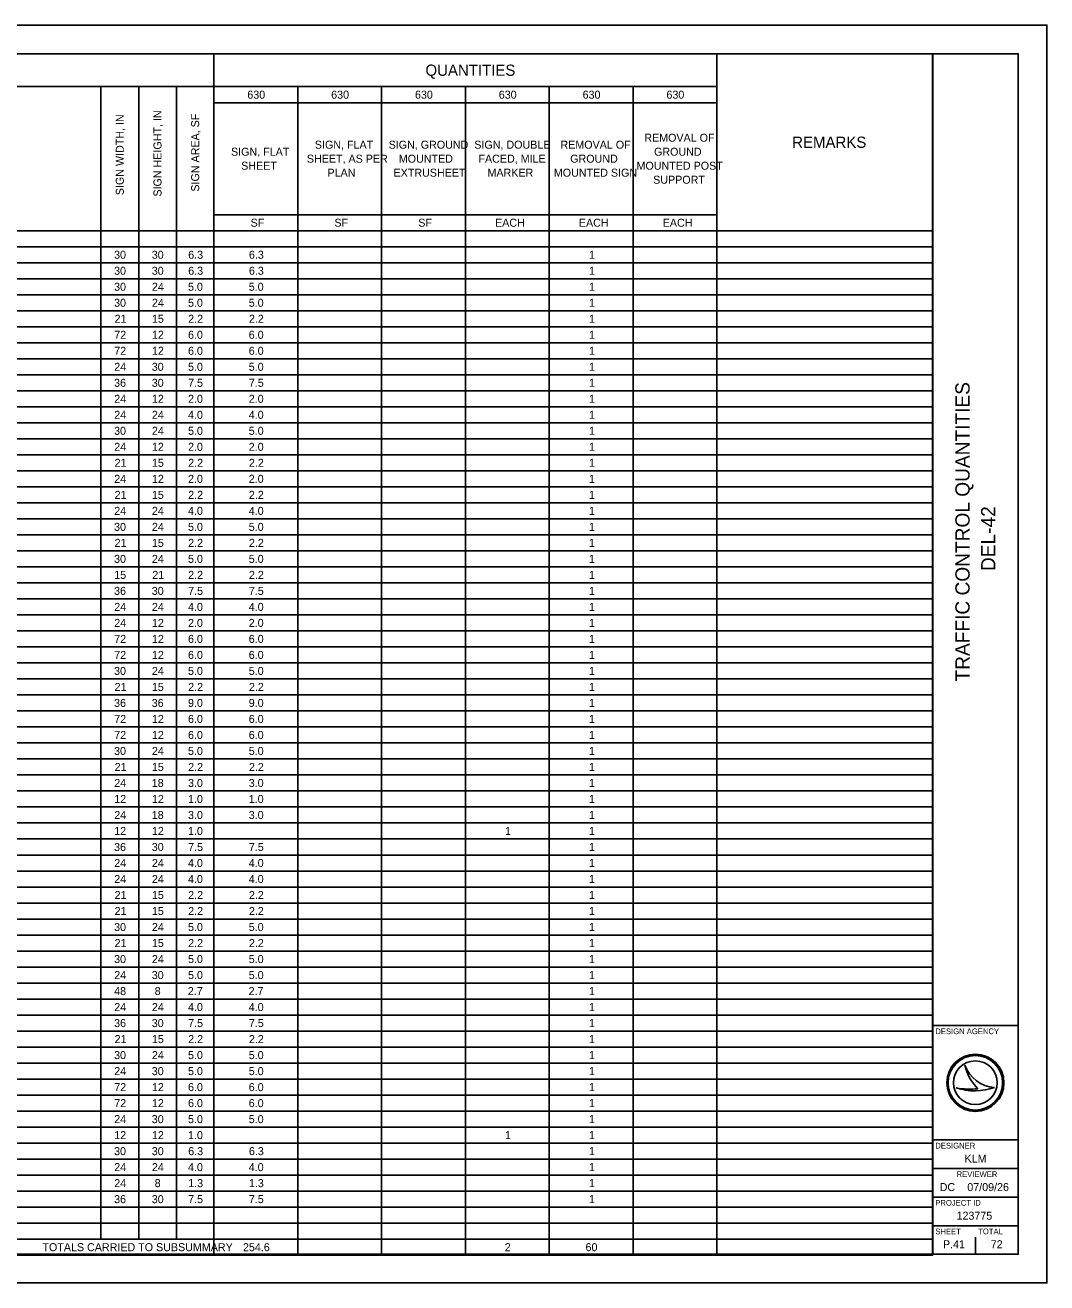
# Model space of a CAD drawing. Extents: x 0 to 34, y 0 to 22.
# Drawn here: x 16.13 to 34, y 0 to 22 of the extents above; entities that cross this region are included whole.
import ezdxf

# ---------------------------------------------------------------- set-up
doc = ezdxf.new("R2010")
doc.units = 0
for name, color, linetype in [('Default', 7, 'Continuous'), ('SH_Border', 7, 'Continuous'), ('SH_Cut_Line', 7, 'Continuous'), ('SH_Data', 7, 'Continuous')]:
    doc.layers.add(name, color=color, linetype=linetype)

msp = doc.modelspace()

# ---------------------------------------------------------------- linework, layer by layer
at = {"layer": 'SH_Border'}
for p, q in [((32, 0.5), (32, 21.5)), ((32, 4.5), (33.5, 4.5)), ((32, 2.5), (33.5, 2.5)), ((32, 2), (33.5, 2)), ((32, 1.5), (33.5, 1.5)), ((32, 1), (33.5, 1))]:
    msp.add_line(p, q, dxfattribs=at)
msp.add_lwpolyline([(1.5, 21.5), (33.5, 21.5), (33.5, 0.5), (1.5, 0.5)], close=True, dxfattribs=at)
at = {"layer": 'SH_Cut_Line'}
msp.add_lwpolyline([(0, 0), (34, 0), (34, 22), (0, 22)], close=True, dxfattribs=at)
at = {"layer": 'SH_Data'}
for p, q in [((1.5, 21.5), (32.004, 21.5)), ((19.436, 21.5), (19.436, 0.484)), ((28.232, 21.5), (28.232, 0.484)), ((32.004, 21.5), (32.004, 0.484)), ((1.5, 20.924), (28.232, 20.924)), ((17.46, 20.924), (17.46, 0.764)), ((18.119, 20.924), (18.119, 0.764)), ((18.778, 20.924), (18.778, 0.764)), ((20.902, 20.924), (20.902, 0.484)), ((22.368, 20.924), (22.368, 0.484)), ((23.834, 20.924), (23.834, 0.484)), ((25.3, 20.924), (25.3, 0.484)), ((26.766, 20.924), (26.766, 0.484)), ((19.436, 20.644), (28.232, 20.644)), ((19.436, 18.684), (28.232, 18.684)), ((1.5, 18.404), (32.004, 18.404)), ((1.5, 18.124), (32.004, 18.124)), ((1.5, 17.844), (32.004, 17.844)), ((1.5, 17.564), (32.004, 17.564)), ((1.5, 17.284), (32.004, 17.284)), ((1.5, 17.004), (32.004, 17.004)), ((1.5, 16.724), (32.004, 16.724)), ((1.5, 16.444), (32.004, 16.444)), ((1.5, 16.164), (32.004, 16.164)), ((1.5, 15.884), (32.004, 15.884)), ((1.5, 15.604), (32.004, 15.604)), ((1.5, 15.324), (32.004, 15.324)), ((1.5, 15.044), (32.004, 15.044)), ((1.5, 14.764), (32.004, 14.764)), ((1.5, 14.484), (32.004, 14.484)), ((1.5, 14.204), (32.004, 14.204)), ((1.5, 13.924), (32.004, 13.924)), ((1.5, 13.644), (32.004, 13.644)), ((1.5, 13.364), (32.004, 13.364)), ((1.5, 13.084), (32.004, 13.084)), ((1.5, 12.804), (32.004, 12.804)), ((1.5, 12.524), (32.004, 12.524)), ((1.5, 12.244), (32.004, 12.244)), ((1.5, 11.964), (32.004, 11.964)), ((1.5, 11.684), (32.004, 11.684)), ((1.5, 11.404), (32.004, 11.404)), ((1.5, 11.124), (32.004, 11.124)), ((1.5, 10.844), (32.004, 10.844)), ((1.5, 10.564), (32.004, 10.564)), ((1.5, 10.284), (32.004, 10.284)), ((1.5, 10.004), (32.004, 10.004)), ((1.5, 9.724), (32.004, 9.724)), ((1.5, 9.444), (32.004, 9.444)), ((1.5, 9.164), (32.004, 9.164)), ((1.5, 8.884), (32.004, 8.884)), ((1.5, 8.604), (32.004, 8.604)), ((1.5, 8.324), (32.004, 8.324)), ((1.5, 8.044), (32.004, 8.044)), ((1.5, 7.764), (32.004, 7.764)), ((1.5, 7.484), (32.004, 7.484)), ((1.5, 7.204), (32.004, 7.204)), ((1.5, 6.924), (32.004, 6.924)), ((1.5, 6.644), (32.004, 6.644)), ((1.5, 6.364), (32.004, 6.364)), ((1.5, 6.084), (32.004, 6.084)), ((1.5, 5.804), (32.004, 5.804)), ((1.5, 5.524), (32.004, 5.524)), ((1.5, 5.244), (32.004, 5.244)), ((1.5, 4.964), (32.004, 4.964)), ((1.5, 4.684), (32.004, 4.684)), ((1.5, 4.404), (32.004, 4.404)), ((1.5, 4.124), (32.004, 4.124)), ((1.5, 3.844), (32.004, 3.844)), ((32.567, 3.81), (32.567, 3.81)), ((1.5, 3.564), (32.004, 3.564)), ((32.417, 3.41), (32.417, 3.41)), ((32.75, 3.5), (32.75, 3.5)), ((33.087, 3.419), (33.087, 3.419)), ((1.5, 3.284), (32.004, 3.284)), ((1.5, 3.004), (32.004, 3.004)), ((1.5, 2.724), (32.004, 2.724)), ((1.5, 2.444), (32.004, 2.444)), ((1.5, 2.164), (32.004, 2.164)), ((1.5, 1.884), (32.004, 1.884)), ((1.5, 1.604), (32.004, 1.604)), ((1.5, 1.324), (32.004, 1.324)), ((1.5, 1.044), (32.004, 1.044)), ((1.5, 0.764), (32.004, 0.764)), ((32.375, 0.675), (32.375, 0.675)), ((32.75, 0.5), (32.75, 0.8)), ((1.5, 0.484), (32.004, 0.484))]:
    msp.add_line(p, q, dxfattribs=at)
for radius in [0.5, 0.477, 0.477, 0.382]:
    msp.add_circle((32.75, 3.5), radius, dxfattribs=at)
for centre, radius, start, end in [((33.116, 3.998), 0.58, 198.9257, 198.9319), ((33.347, 3.97), 0.796, 191.6379, 191.6421), ((33.116, 3.998), 0.58, 198.9319, 267.1657), ((33.347, 3.97), 0.796, 191.6421, 226.0947), ((32.739, 4.37), 1.013, 251.4576, 290.0832), ((32.648, 4.654), 1.266, 259.4964, 259.4995), ((32.739, 4.37), 1.013, 251.4527, 251.4576), ((32.648, 4.654), 1.266, 259.4995, 276.6672)]:
    msp.add_arc(centre, radius, start, end, dxfattribs=at)

# ---------------------------------------------------------------- texts
at = {"layer": 'Default'}
for s, height, p in [('QUANTITIES', 0.196, (23.134, 21.114)), ('630', 0.14, (20.019, 20.714)), ('630', 0.14, (21.485, 20.714)), ('630', 0.14, (22.951, 20.714)), ('630', 0.14, (24.416, 20.714)), ('630', 0.14, (25.882, 20.714)), ('630', 0.14, (27.348, 20.714)), ('REMOVAL OF ', 0.14, (26.961, 19.961)), ('REMARKS', 0.196, (29.547, 19.854)), ('SIGN, FLAT ', 0.14, (19.734, 19.716)), ('SIGN, FLAT ', 0.14, (21.2, 19.839)), ('SIGN, GROUND ', 0.14, (22.49, 19.839)), ('SIGN, DOUBLE ', 0.14, (23.988, 19.839)), ('REMOVAL OF ', 0.14, (25.495, 19.839)), ('GROUND ', 0.14, (27.131, 19.716)), ('SHEET', 0.14, (19.911, 19.471)), ('SHEET, AS PER ', 0.14, (21.06, 19.594)), ('MOUNTED ', 0.14, (22.668, 19.594)), ('FACED, MILE ', 0.14, (24.061, 19.594)), ('GROUND ', 0.14, (25.665, 19.594)), ('MOUNTED POST ', 0.14, (26.825, 19.471)), ('PLAN', 0.14, (21.421, 19.349)), ('EXTRUSHEET', 0.14, (22.576, 19.349)), ('MARKER', 0.14, (24.219, 19.349)), ('MOUNTED SIGN', 0.14, (25.379, 19.349)), ('SUPPORT', 0.14, (27.116, 19.226)), ('SF', 0.14, (20.076, 18.474)), ('SF', 0.14, (21.542, 18.474)), ('SF', 0.14, (23.008, 18.474)), ('EACH', 0.14, (24.351, 18.474)), ('EACH', 0.14, (25.817, 18.474)), ('EACH', 0.14, (27.283, 18.474)), ('30', 0.14, (17.689, 17.914)), ('30', 0.14, (18.348, 17.914)), ('6.3', 0.14, (18.985, 17.914)), ('6.3', 0.14, (20.047, 17.914)), ('1', 0.14, (25.992, 17.914)), ('30', 0.14, (17.689, 17.634)), ('30', 0.14, (18.348, 17.634)), ('6.3', 0.14, (18.985, 17.634)), ('6.3', 0.14, (20.047, 17.634)), ('1', 0.14, (25.992, 17.634)), ('30', 0.14, (17.689, 17.354)), ('24', 0.14, (18.351, 17.354)), ('5.0', 0.14, (18.982, 17.354)), ('5.0', 0.14, (20.044, 17.354)), ('1', 0.14, (25.992, 17.354)), ('30', 0.14, (17.689, 17.074)), ('24', 0.14, (18.351, 17.074)), ('5.0', 0.14, (18.982, 17.074)), ('5.0', 0.14, (20.044, 17.074)), ('1', 0.14, (25.992, 17.074)), ('21', 0.14, (17.698, 16.794)), ('15', 0.14, (18.35, 16.794)), ('2.2', 0.14, (18.985, 16.794)), ('2.2', 0.14, (20.047, 16.794)), ('1', 0.14, (25.992, 16.794)), ('72', 0.14, (17.692, 16.514)), ('12', 0.14, (18.351, 16.514)), ('6.0', 0.14, (18.982, 16.514)), ('6.0', 0.14, (20.044, 16.514)), ('1', 0.14, (25.992, 16.514)), ('72', 0.14, (17.692, 16.234)), ('12', 0.14, (18.351, 16.234)), ('6.0', 0.14, (18.982, 16.234)), ('6.0', 0.14, (20.044, 16.234)), ('1', 0.14, (25.992, 16.234)), ('24', 0.14, (17.692, 15.954)), ('30', 0.14, (18.348, 15.954)), ('5.0', 0.14, (18.982, 15.954)), ('5.0', 0.14, (20.044, 15.954)), ('1', 0.14, (25.992, 15.954)), ('36', 0.14, (17.689, 15.674)), ('30', 0.14, (18.348, 15.674)), ('7.5', 0.14, (18.984, 15.674)), ('7.5', 0.14, (20.046, 15.674)), ('1', 0.14, (25.992, 15.674)), ('24', 0.14, (17.692, 15.394)), ('12', 0.14, (18.351, 15.394)), ('2.0', 0.14, (18.982, 15.394)), ('2.0', 0.14, (20.044, 15.394)), ('1', 0.14, (25.992, 15.394)), ('24', 0.14, (17.692, 15.114)), ('24', 0.14, (18.351, 15.114)), ('4.0', 0.14, (18.982, 15.114)), ('4.0', 0.14, (20.044, 15.114)), ('1', 0.14, (25.992, 15.114)), ('30', 0.14, (17.689, 14.834)), ('24', 0.14, (18.351, 14.834)), ('5.0', 0.14, (18.982, 14.834)), ('5.0', 0.14, (20.044, 14.834)), ('1', 0.14, (25.992, 14.834)), ('24', 0.14, (17.692, 14.554)), ('12', 0.14, (18.351, 14.554)), ('2.0', 0.14, (18.982, 14.554)), ('2.0', 0.14, (20.044, 14.554)), ('1', 0.14, (25.992, 14.554)), ('21', 0.14, (17.698, 14.274)), ('15', 0.14, (18.35, 14.274)), ('2.2', 0.14, (18.985, 14.274)), ('2.2', 0.14, (20.047, 14.274)), ('1', 0.14, (25.992, 14.274)), ('24', 0.14, (17.692, 13.994)), ('12', 0.14, (18.351, 13.994)), ('2.0', 0.14, (18.982, 13.994)), ('2.0', 0.14, (20.044, 13.994)), ('1', 0.14, (25.992, 13.994)), ('21', 0.14, (17.698, 13.714)), ('15', 0.14, (18.35, 13.714)), ('2.2', 0.14, (18.985, 13.714)), ('2.2', 0.14, (20.047, 13.714)), ('1', 0.14, (25.992, 13.714)), ('24', 0.14, (17.692, 13.434)), ('24', 0.14, (18.351, 13.434)), ('4.0', 0.14, (18.982, 13.434)), ('4.0', 0.14, (20.044, 13.434)), ('1', 0.14, (25.992, 13.434)), ('30', 0.14, (17.689, 13.154)), ('24', 0.14, (18.351, 13.154)), ('5.0', 0.14, (18.982, 13.154)), ('5.0', 0.14, (20.044, 13.154)), ('1', 0.14, (25.992, 13.154)), ('21', 0.14, (17.698, 12.874)), ('15', 0.14, (18.35, 12.874)), ('2.2', 0.14, (18.985, 12.874)), ('2.2', 0.14, (20.047, 12.874)), ('1', 0.14, (25.992, 12.874)), ('30', 0.14, (17.689, 12.594)), ('24', 0.14, (18.351, 12.594)), ('5.0', 0.14, (18.982, 12.594)), ('5.0', 0.14, (20.044, 12.594)), ('1', 0.14, (25.992, 12.594)), ('15', 0.14, (17.691, 12.314)), ('21', 0.14, (18.357, 12.314)), ('2.2', 0.14, (18.985, 12.314)), ('2.2', 0.14, (20.047, 12.314)), ('1', 0.14, (25.992, 12.314)), ('36', 0.14, (17.689, 12.034)), ('30', 0.14, (18.348, 12.034)), ('7.5', 0.14, (18.984, 12.034)), ('7.5', 0.14, (20.046, 12.034)), ('1', 0.14, (25.992, 12.034)), ('24', 0.14, (17.692, 11.754)), ('24', 0.14, (18.351, 11.754)), ('4.0', 0.14, (18.982, 11.754)), ('4.0', 0.14, (20.044, 11.754)), ('1', 0.14, (25.992, 11.754)), ('24', 0.14, (17.692, 11.474)), ('12', 0.14, (18.351, 11.474)), ('2.0', 0.14, (18.982, 11.474)), ('2.0', 0.14, (20.044, 11.474)), ('1', 0.14, (25.992, 11.474)), ('72', 0.14, (17.692, 11.194)), ('12', 0.14, (18.351, 11.194)), ('6.0', 0.14, (18.982, 11.194)), ('6.0', 0.14, (20.044, 11.194)), ('1', 0.14, (25.992, 11.194)), ('72', 0.14, (17.692, 10.914)), ('12', 0.14, (18.351, 10.914)), ('6.0', 0.14, (18.982, 10.914)), ('6.0', 0.14, (20.044, 10.914)), ('1', 0.14, (25.992, 10.914)), ('30', 0.14, (17.689, 10.634)), ('24', 0.14, (18.351, 10.634)), ('5.0', 0.14, (18.982, 10.634)), ('5.0', 0.14, (20.044, 10.634)), ('1', 0.14, (25.992, 10.634)), ('21', 0.14, (17.698, 10.354)), ('15', 0.14, (18.35, 10.354)), ('2.2', 0.14, (18.985, 10.354)), ('2.2', 0.14, (20.047, 10.354)), ('1', 0.14, (25.992, 10.354)), ('36', 0.14, (17.689, 10.074)), ('36', 0.14, (18.347, 10.074)), ('9.0', 0.14, (18.982, 10.074)), ('9.0', 0.14, (20.044, 10.074)), ('1', 0.14, (25.992, 10.074)), ('72', 0.14, (17.692, 9.794)), ('12', 0.14, (18.351, 9.794)), ('6.0', 0.14, (18.982, 9.794)), ('6.0', 0.14, (20.044, 9.794)), ('1', 0.14, (25.992, 9.794)), ('72', 0.14, (17.692, 9.514)), ('12', 0.14, (18.351, 9.514)), ('6.0', 0.14, (18.982, 9.514)), ('6.0', 0.14, (20.044, 9.514)), ('1', 0.14, (25.992, 9.514)), ('30', 0.14, (17.689, 9.234)), ('24', 0.14, (18.351, 9.234)), ('5.0', 0.14, (18.982, 9.234)), ('5.0', 0.14, (20.044, 9.234)), ('1', 0.14, (25.992, 9.234)), ('21', 0.14, (17.698, 8.954)), ('15', 0.14, (18.35, 8.954)), ('2.2', 0.14, (18.985, 8.954)), ('2.2', 0.14, (20.047, 8.954)), ('1', 0.14, (25.992, 8.954)), ('24', 0.14, (17.692, 8.674)), ('18', 0.14, (18.348, 8.674)), ('3.0', 0.14, (18.982, 8.674)), ('3.0', 0.14, (20.044, 8.674)), ('1', 0.14, (25.992, 8.674)), ('12', 0.14, (17.692, 8.394)), ('12', 0.14, (18.351, 8.394)), ('1.0', 0.14, (18.982, 8.394)), ('1.0', 0.14, (20.044, 8.394)), ('1', 0.14, (25.992, 8.394)), ('24', 0.14, (17.692, 8.114)), ('18', 0.14, (18.348, 8.114)), ('3.0', 0.14, (18.982, 8.114)), ('3.0', 0.14, (20.044, 8.114)), ('1', 0.14, (25.992, 8.114)), ('12', 0.14, (17.692, 7.834)), ('12', 0.14, (18.351, 7.834)), ('1.0', 0.14, (18.982, 7.834)), ('1', 0.14, (24.526, 7.834)), ('1', 0.14, (25.992, 7.834)), ('36', 0.14, (17.689, 7.554)), ('30', 0.14, (18.348, 7.554)), ('7.5', 0.14, (18.984, 7.554)), ('7.5', 0.14, (20.046, 7.554)), ('1', 0.14, (25.992, 7.554)), ('24', 0.14, (17.692, 7.274)), ('24', 0.14, (18.351, 7.274)), ('4.0', 0.14, (18.982, 7.274)), ('4.0', 0.14, (20.044, 7.274)), ('1', 0.14, (25.992, 7.274)), ('24', 0.14, (17.692, 6.994)), ('24', 0.14, (18.351, 6.994)), ('4.0', 0.14, (18.982, 6.994)), ('4.0', 0.14, (20.044, 6.994)), ('1', 0.14, (25.992, 6.994)), ('21', 0.14, (17.698, 6.714)), ('15', 0.14, (18.35, 6.714)), ('2.2', 0.14, (18.985, 6.714)), ('2.2', 0.14, (20.047, 6.714)), ('1', 0.14, (25.992, 6.714)), ('21', 0.14, (17.698, 6.434)), ('15', 0.14, (18.35, 6.434)), ('2.2', 0.14, (18.985, 6.434)), ('2.2', 0.14, (20.047, 6.434)), ('1', 0.14, (25.992, 6.434)), ('30', 0.14, (17.689, 6.154)), ('24', 0.14, (18.351, 6.154)), ('5.0', 0.14, (18.982, 6.154)), ('5.0', 0.14, (20.044, 6.154)), ('1', 0.14, (25.992, 6.154)), ('21', 0.14, (17.698, 5.874)), ('15', 0.14, (18.35, 5.874)), ('2.2', 0.14, (18.985, 5.874)), ('2.2', 0.14, (20.047, 5.874)), ('1', 0.14, (25.992, 5.874)), ('30', 0.14, (17.689, 5.594)), ('24', 0.14, (18.351, 5.594)), ('5.0', 0.14, (18.982, 5.594)), ('5.0', 0.14, (20.044, 5.594)), ('1', 0.14, (25.992, 5.594)), ('24', 0.14, (17.692, 5.314)), ('30', 0.14, (18.348, 5.314)), ('5.0', 0.14, (18.982, 5.314)), ('5.0', 0.14, (20.044, 5.314)), ('1', 0.14, (25.992, 5.314)), ('48', 0.14, (17.69, 5.034)), ('8', 0.14, (18.399, 5.034)), ('2.7', 0.14, (18.979, 5.034)), ('2.7', 0.14, (20.041, 5.034)), ('1', 0.14, (25.992, 5.034)), ('24', 0.14, (17.692, 4.754)), ('24', 0.14, (18.351, 4.754)), ('4.0', 0.14, (18.982, 4.754)), ('4.0', 0.14, (20.044, 4.754)), ('1', 0.14, (25.992, 4.754)), ('36', 0.14, (17.689, 4.474)), ('30', 0.14, (18.348, 4.474)), ('7.5', 0.14, (18.984, 4.474)), ('7.5', 0.14, (20.046, 4.474)), ('1', 0.14, (25.992, 4.474)), ('21', 0.14, (17.698, 4.194)), ('15', 0.14, (18.35, 4.194)), ('2.2', 0.14, (18.985, 4.194)), ('2.2', 0.14, (20.047, 4.194)), ('1', 0.14, (25.992, 4.194)), ('30', 0.14, (17.689, 3.914)), ('24', 0.14, (18.351, 3.914)), ('5.0', 0.14, (18.982, 3.914)), ('5.0', 0.14, (20.044, 3.914)), ('1', 0.14, (25.992, 3.914)), ('24', 0.14, (17.692, 3.634)), ('30', 0.14, (18.348, 3.634)), ('5.0', 0.14, (18.982, 3.634)), ('5.0', 0.14, (20.044, 3.634)), ('1', 0.14, (25.992, 3.634)), ('72', 0.14, (17.692, 3.354)), ('12', 0.14, (18.351, 3.354)), ('6.0', 0.14, (18.982, 3.354)), ('6.0', 0.14, (20.044, 3.354)), ('1', 0.14, (25.992, 3.354)), ('72', 0.14, (17.692, 3.074)), ('12', 0.14, (18.351, 3.074)), ('6.0', 0.14, (18.982, 3.074)), ('6.0', 0.14, (20.044, 3.074)), ('1', 0.14, (25.992, 3.074)), ('24', 0.14, (17.692, 2.794)), ('30', 0.14, (18.348, 2.794)), ('5.0', 0.14, (18.982, 2.794)), ('5.0', 0.14, (20.044, 2.794)), ('1', 0.14, (25.992, 2.794)), ('12', 0.14, (17.692, 2.514)), ('12', 0.14, (18.351, 2.514)), ('1.0', 0.14, (18.982, 2.514)), ('1', 0.14, (24.526, 2.514)), ('1', 0.14, (25.992, 2.514)), ('30', 0.14, (17.689, 2.234)), ('30', 0.14, (18.348, 2.234)), ('6.3', 0.14, (18.985, 2.234)), ('6.3', 0.14, (20.047, 2.234)), ('1', 0.14, (25.992, 2.234)), ('24', 0.14, (17.692, 1.954)), ('24', 0.14, (18.351, 1.954)), ('4.0', 0.14, (18.982, 1.954)), ('4.0', 0.14, (20.044, 1.954)), ('1', 0.14, (25.992, 1.954)), ('24', 0.14, (17.692, 1.674)), ('8', 0.14, (18.399, 1.674)), ('1.3', 0.14, (18.985, 1.674)), ('1.3', 0.14, (20.047, 1.674)), ('1', 0.14, (25.992, 1.674)), ('36', 0.14, (17.689, 1.394)), ('30', 0.14, (18.348, 1.394)), ('7.5', 0.14, (18.984, 1.394)), ('7.5', 0.14, (20.046, 1.394)), ('1', 0.14, (25.992, 1.394)), ('TOTALS CARRIED TO SUBSUMMARY', 0.14, (16.436, 0.554)), ('254.6', 0.14, (19.943, 0.554)), ('2', 0.14, (24.52, 0.554)), ('60', 0.14, (25.933, 0.554))]:
    msp.add_text(s, height=height, dxfattribs=at).set_placement(p)
for s, p in [('SIGN HEIGHT, IN', (18.518, 19.001)), ('SIGN WIDTH, IN', (17.859, 19.026)), ('SIGN AREA, SF', (19.177, 19.088))]:
    msp.add_text(s, height=0.14, rotation=90, dxfattribs=at).set_placement(p)
at = {"layer": 'SH_Data'}
for s, p in [('TRAFFIC CONTROL QUANTITIES', (32.65, 10.519)), ('DEL-42', (33.1, 12.451))]:
    msp.add_text(s, height=0.25, rotation=90, dxfattribs=at).set_placement(p)
for s, height, p in [('DESIGN AGENCY', 0.1, (32.05, 4.35)), ('DESIGNER', 0.1, (32.05, 2.35)), ('KLM', 0.14, (32.561, 2.105)), ('REVIEWER', 0.1, (32.422, 1.85)), ('DC', 0.14, (32.126, 1.605)), ('07/09/26', 0.14, (32.609, 1.605)), ('PROJECT ID', 0.1, (32.05, 1.35)), ('123775', 0.14, (32.421, 1.105)), ('SHEET', 0.1, (32.05, 0.85)), ('TOTAL', 0.1, (32.8, 0.85)), ('P.41', 0.14, (32.184, 0.605)), ('72', 0.14, (33.019, 0.605))]:
    msp.add_text(s, height=height, dxfattribs=at).set_placement(p)

doc.saveas('drawing.dxf')
